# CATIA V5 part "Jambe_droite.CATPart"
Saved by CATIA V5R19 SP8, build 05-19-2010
Part number: Jambe_droite
Bounding box of the stored display mesh (mm): x 651.003 to 895, y -2625 to -1075, z -150 to 190
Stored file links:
  G:\EU_thinkMotion\CFAO_2010\MMS_groupe2\MMS_groupe2\OK\mmartini\mmartiniCFAO\Jambe_droite.CATPart
  C:\Users\Mathieu Martini\Desktop\CFAO\Animation\CFAO.CATProduct
  G:\EU_thinkMotion\CFAO_2010\MMS_groupe2\MMS_groupe2\OK\mmartini\mmartiniCFAO\Squelette.CATPart
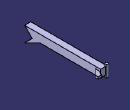
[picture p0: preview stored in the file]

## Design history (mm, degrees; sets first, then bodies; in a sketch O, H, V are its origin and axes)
External parameters (linked from other documents)
  External.diametre_canon = 150 mm
  External.diametre_verin = 120 mm
AxisSystem1: origin (0, 0, 0), X (1, 0, 0), Y (0, 1, 0), Z (0, 0, 1)
Set1
  Sketch1 on Plane1, origin (675, 0, 0), H (0, 1, 0), V (0, 0, 1)
    line L1 (-1125, 150) -> (-2475, 150)
    line L2 (-2475, 150) -> (-2475, 0)
    line L3 (-2475, 0) -> (-1125, 0)
    line L4 (-1125, 0) -> (-1125, 150)
    point P3 (-2475, 0)
    reference projected point E1 (-900, 150) from Line1
    length L4 = 150 {= External.diametre_canon}
    distance E1 L4 = 225 {= External.diametre_canon *1.5}
    distance L4 L2 = 1350 {= External.diametre_canon *9}
    horizontal: L1 H, L3 H
    vertical: L2 V, L4 V
    coincidence: P3 H
Set2
  Plane1 "Plan_verin_droit": linked copy from another document
  Line1 "axe_berceau_jambe": linked copy from another document
Body1 (main body)
  Pad1: profile Sketch1, direction (1, 0, 0), length 120 {= External.diametre_verin}
  Sketch2 on face of Pad1 from Sketch1.L4, origin (0, -1125, 0), H (-1, 0, 0), V (0, 0, 1)
    point P1 (-675, 190)
    line L1 (-675, 190) -> (-699, 190)
    line L2 (-699, 190) -> (-699, -40)
    projected line E1 (-675, 0) -> (-795, 0) from edge [face of Pad1 from Sketch1.L4 | face of Pad1 from Sketch1.L3]
    line L3 (-699, -40) -> (-675, -40)
    line L4 (-675, -40) -> (-675, 190)
    point P7 (-675, 190)
    reference projected line E2 (-675, 0) -> (-675, 150) from edge [start face of Pad1 | face of Pad1 from Sketch1.L4]
    reference projected line E3 (-675, 150) -> (-825, 150) from edge [face of Pad1 from Sketch1.L1 | face of Pad1 from Sketch1.L4]
    distance E3 L1 = 40 {= External.diametre_verin /3}
    distance E1 L3 = 40 {= External.diametre_verin /3}
    distance L4 L2 = 24 {= External.diametre_verin /5}
    horizontal: L1 H, L3 H
    vertical: L2 V, L4 V
    coincidence: P7 L1, P1 P7, E2 L4
  Shaft1: profile Sketch2, axis Sketch2.L4, angle 360
  Sketch3 on end face of Pad1, origin (795, 0, 0), H (0, 1, 0), V (0, 0, 1)
    axis line L1 (-1359.773, 75) -> (-1123.4756, 75)
    reference projected line E1 (-2475, 0) -> (-1125, 0) from edge [face of Pad1 from Sketch1.L3 | end face of Pad1]
    line L2 (-1225, 112.5) -> (-1225, 37.5)
    point P3 (-1225, 112.5)
    line L3 (-1225, 112.5) -> (-1075, 93.75)
    point P5 (-1075, 93.75)
    line L4 (-1075, 93.75) -> (-1075, 56.25)
    line L5 (-1075, 56.25) -> (-1225, 37.5)
    reference projected line E2 (-1125, 0) -> (-1125, 150) from edge [face of Pad1 from Sketch1.L4 | end face of Pad1]
    distance L1 E1 = 75 {= External.diametre_canon /2}
    length L5 H = 150 {= External.diametre_canon}
    length L2 = 75 {= External.diametre_canon /2}
    length L4 = 37.5 {= External.diametre_canon /4}
    distance L1 P3 = 37.5 {= External.diametre_canon /4}
    distance P5 L1 = 18.75 {= External.diametre_canon /8}
    distance E2 L4 = 50 {= External.diametre_canon /3}
    horizontal: L1 H
    vertical: L2 V, L4 V
  Sketch4 on face of Pad1 from Sketch1.L1, origin (0, 0, 150), H (1, 0, 0), V (0, 1, 0)
    line L1 (820, -1075) -> (820, -1100)
    point P1 (820, -1075)
    reference projected line E1 (675, -1125) -> (795, -1125) from edge [face of Pad1 from Sketch1.L1 | face of Pad1 from Sketch1.L4]
    arc A1 centre (795, -1100) radius 25 from (795, -1125) to (820, -1100) ccw
    point P2 (795, -1100)
    reference projected line E2 (675, -1125) -> (795, -1125) from edge [face of Pad1 from Sketch1.L1 | face of Pad1 from Sketch1.L4]
    reference projected line E3 (675, -1125) -> (795, -1125) from edge [face of Pad1 from Sketch1.L1 | face of Pad1 from Sketch1.L4]
    axis line L2 (795, -1149.3658) -> (795, -1089.7544)
    reference projected line E4 (795, -1125) -> (795, -2475) from edge [face of Pad1 from Sketch1.L1 | end face of Pad1]
    point P5 (795, -1125)
    line L3 (795, -1125) -> (795, -1225)
    point P7 (795, -1275)
    line L4 (820, -1075) -> (895, -1075)
    point P8 (895, -1075)
    line L5 (895, -1075) -> (895, -1125)
    point P10 (795, -1225)
    line L6 (895, -1125) -> (795, -1225)
    distance P1 E1 = 50 {= External.diametre_canon /3}
    distance P2 E2 = 25 {= External.diametre_canon /6}
    length L4 = 75 {= External.diametre_canon /2}
    distance P8 P10 V = 150 {= External.diametre_canon}
    length L5 = 50 {= External.diametre_canon /3}
    vertical: L1 V, L2 V, L3 V, L5 V
    tangency: A1 L1, E3 A1, L4 A1
    coincidence: L2 E4, P2 L2, L2 P5
  SolidCombine1: FirstComponentProfile Sketch3, FirstComponentDirection Sketch3, SecondComponentProfile Sketch4, SecondComponentDirection Sketch4
  Sketch5 on start face of Pad1, origin (675, 0, 0), H (0, -1, 0), V (0, 0, 1)
    line L1 (2475, 0) -> (2625, -150)
    point P1 (2475, 0)
    reference projected line E1 (2475, 150) -> (2475, 0) from edge [start face of Pad1 | face of Pad1 from Sketch1.L2]
    reference projected line E2 (2475, 0) -> (1125, 0) from edge [start face of Pad1 | face of Pad1 from Sketch1.L3]
    line L2 (2475, 0) -> (2625, 150)
    point P3 (2625, 150)
    reference projected line E3 (1125, 150) -> (2475, 150) from edge [start face of Pad1 | face of Pad1 from Sketch1.L1]
    projected line E4 (2475, 150) -> (2475, 0) from edge [start face of Pad1 | face of Pad1 from Sketch1.L2]
    point P5 (2475, 0)
    line L3 (2475, 150) -> (2625, 150)
    point P6 (2625, 150)
    line L4 (2625, -150) -> (2325, 0)
    point P7 (2325, 0)
    line L5 (2325, 0) -> (2475, 0)
    length L1 H = 150 {= External.diametre_canon}
    length L1 V = 150 {= External.diametre_canon}
    length L5 = 150 {= External.diametre_canon}
    coincidence: E1 P1, E2 P1, P3 E3, P6 L2, P7 H, P1 P5, P3 P6
    perpendicularity: L2 L1
    horizontal: L3 H, L5 H
  Pad2: profile Sketch5, direction (-1, 0, 0), up to end face of Pad1
  Point1: (0, 0, 0), relative to vertex [face of Pad2 from Sketch5.L1 | face of Pad1 | face of Pad2 from Sketch5.L2], in AxisSystem1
